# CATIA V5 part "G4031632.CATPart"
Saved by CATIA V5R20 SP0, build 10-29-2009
Part number: G4031632
Revision: 3
Definition: design
Nomenclature: G4031632
Source: made
Description: NOT SPECIFIED
Bounding box of the stored display mesh (mm): x -16 to 16, y -12.803 to 12.803, z -13 to 13
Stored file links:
  C:\Users\Raffaele\Desktop\3D X SITO CF\BOLEX\27-BUSH REF 403\G4031632.CATPart
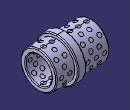
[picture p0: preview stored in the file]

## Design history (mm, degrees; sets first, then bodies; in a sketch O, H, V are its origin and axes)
Body1 "MANIFOLD_SOLID_BREP #8737" (main body)
  Solid1: solid without history
Body2 "MANIFOLD_SOLID_BREP #8880"
  Solid2: solid without history
Body3 "MANIFOLD_SOLID_BREP #9023"
  Solid3: solid without history
Body4 "MANIFOLD_SOLID_BREP #9166"
  Solid4: solid without history
Body5 "MANIFOLD_SOLID_BREP #9309"
  Solid5: solid without history
Body6 "MANIFOLD_SOLID_BREP #9454"
  Solid6: solid without history
Body7 "MANIFOLD_SOLID_BREP #9599"
  Solid7: solid without history
Body8 "MANIFOLD_SOLID_BREP #9744"
  Solid8: solid without history
Body9 "MANIFOLD_SOLID_BREP #9889"
  Solid9: solid without history
Body10 "MANIFOLD_SOLID_BREP #10034"
  Solid10: solid without history
Body11 "MANIFOLD_SOLID_BREP #10179"
  Solid11: solid without history
Body12 "MANIFOLD_SOLID_BREP #10324"
  Solid12: solid without history
Body13 "MANIFOLD_SOLID_BREP #10469"
  Solid13: solid without history
Body14 "MANIFOLD_SOLID_BREP #10614"
  Solid14: solid without history
Body15 "MANIFOLD_SOLID_BREP #10759"
  Solid15: solid without history
Body16 "MANIFOLD_SOLID_BREP #10904"
  Solid16: solid without history
Body17 "MANIFOLD_SOLID_BREP #11049"
  Solid17: solid without history
Body18 "MANIFOLD_SOLID_BREP #11192"
  Solid18: solid without history
Body19 "MANIFOLD_SOLID_BREP #11335"
  Solid19: solid without history
Body20 "MANIFOLD_SOLID_BREP #11478"
  Solid20: solid without history
Body21 "MANIFOLD_SOLID_BREP #11622"
  Solid21: solid without history
Body22 "MANIFOLD_SOLID_BREP #11767"
  Solid22: solid without history
Body23 "MANIFOLD_SOLID_BREP #11910"
  Solid23: solid without history
Body24 "MANIFOLD_SOLID_BREP #12054"
  Solid24: solid without history
Body25 "MANIFOLD_SOLID_BREP #12199"
  Solid25: solid without history
Body26 "MANIFOLD_SOLID_BREP #12344"
  Solid26: solid without history
Body27 "MANIFOLD_SOLID_BREP #12489"
  Solid27: solid without history
Body28 "MANIFOLD_SOLID_BREP #12634"
  Solid28: solid without history
Body29 "MANIFOLD_SOLID_BREP #12779"
  Solid29: solid without history
Body30 "MANIFOLD_SOLID_BREP #12924"
  Solid30: solid without history
Body31 "MANIFOLD_SOLID_BREP #13069"
  Solid31: solid without history
Body32 "MANIFOLD_SOLID_BREP #13212"
  Solid32: solid without history
Body33 "MANIFOLD_SOLID_BREP #13355"
  Solid33: solid without history
Body34 "MANIFOLD_SOLID_BREP #13500"
  Solid34: solid without history
Body35 "MANIFOLD_SOLID_BREP #13645"
  Solid35: solid without history
Body36 "MANIFOLD_SOLID_BREP #13790"
  Solid36: solid without history
Body37 "MANIFOLD_SOLID_BREP #13935"
  Solid37: solid without history
Body38 "MANIFOLD_SOLID_BREP #14080"
  Solid38: solid without history
Body39 "MANIFOLD_SOLID_BREP #14225"
  Solid39: solid without history
Body40 "MANIFOLD_SOLID_BREP #14370"
  Solid40: solid without history
Body41 "MANIFOLD_SOLID_BREP #14515"
  Solid41: solid without history
Body42 "MANIFOLD_SOLID_BREP #14660"
  Solid42: solid without history
Body43 "MANIFOLD_SOLID_BREP #14805"
  Solid43: solid without history
Body44 "MANIFOLD_SOLID_BREP #14950"
  Solid44: solid without history
Body45 "MANIFOLD_SOLID_BREP #15095"
  Solid45: solid without history
Body46 "MANIFOLD_SOLID_BREP #15238"
  Solid46: solid without history
Body47 "MANIFOLD_SOLID_BREP #15381"
  Solid47: solid without history
Body48 "MANIFOLD_SOLID_BREP #15524"
  Solid48: solid without history
Body49 "MANIFOLD_SOLID_BREP #15668"
  Solid49: solid without history
Body50 "MANIFOLD_SOLID_BREP #15813"
  Solid50: solid without history
Body51 "MANIFOLD_SOLID_BREP #15956"
  Solid51: solid without history
Body52 "MANIFOLD_SOLID_BREP #16100"
  Solid52: solid without history
Body53 "MANIFOLD_SOLID_BREP #16245"
  Solid53: solid without history
Body54 "MANIFOLD_SOLID_BREP #16388"
  Solid54: solid without history
Body55 "MANIFOLD_SOLID_BREP #16531"
  Solid55: solid without history
Body56 "MANIFOLD_SOLID_BREP #16674"
  Solid56: solid without history
Body57 "MANIFOLD_SOLID_BREP #16817"
  Solid57: solid without history
Body58 "MANIFOLD_SOLID_BREP #16960"
  Solid58: solid without history
Body59 "MANIFOLD_SOLID_BREP #17103"
  Solid59: solid without history
Body60 "MANIFOLD_SOLID_BREP #17246"
  Solid60: solid without history
Body61 "MANIFOLD_SOLID_BREP #17390"
  Solid61: solid without history
Body62 "MANIFOLD_SOLID_BREP #17535"
  Solid62: solid without history
Body63 "MANIFOLD_SOLID_BREP #17678"
  Solid63: solid without history
Body64 "MANIFOLD_SOLID_BREP #17822"
  Solid64: solid without history
Body65 "MANIFOLD_SOLID_BREP #17967"
  Solid65: solid without history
